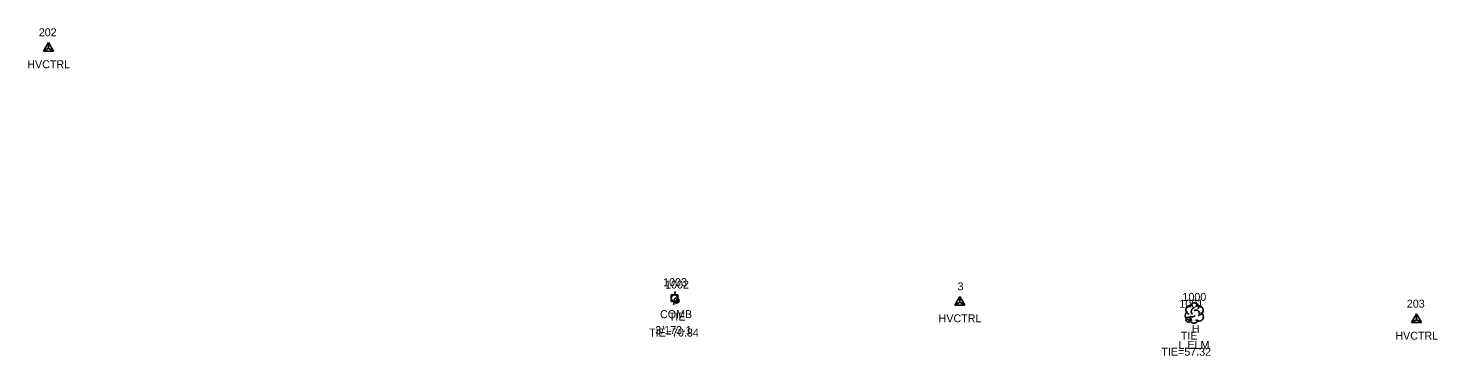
# Model space of a CAD drawing. Extents: x 1505684 to 1510253, y 730355 to 731397.
# Drawn here: x 1508083.3 to 1508435.7, y 730355.2 to 730437.1 of the extents above; entities that cross this region are included whole.
import ezdxf

# ---------------------------------------------------------------- set-up
doc = ezdxf.new("R2010")
doc.units = 0
for name, color, linetype in [('C_A', 7, 'Continuous'), ('C_C', 7, 'Continuous'), ('C_I', 7, 'Continuous'), ('CBP', 7, 'Continuous'), ('CPSM', 7, 'Continuous'), ('L_A', 7, 'Continuous'), ('L_C', 7, 'Continuous'), ('L_I', 7, 'Continuous'), ('LTD', 7, 'Continuous'), ('U_A', 7, 'Continuous'), ('U_C', 7, 'Continuous'), ('U_I', 7, 'Continuous'), ('UP', 7, 'Continuous')]:
    doc.layers.add(name, color=color, linetype=linetype)

msp = doc.modelspace()

# ---------------------------------------------------------------- linework, layer by layer
at = {"layer": 'CBP'}
for centre, radius in [((1508245.36, 730369.01), 0.625), ((1508245.36, 730369.01), 0.0833), ((1508373.34, 730364.22), 0.625), ((1508373.34, 730364.22), 0.0833)]:
    msp.add_circle(centre, radius, dxfattribs=at)
at = {"layer": 'CPSM'}
for p, q in [((1508087.13, 730431.37), (1508088.38, 730433.53)), ((1508089.63, 730431.37), (1508088.38, 730433.53)), ((1508088.38, 730432.09), (1508088.38, 730433.53)), ((1508087.13, 730431.37), (1508088.38, 730432.09)), ((1508087.13, 730431.37), (1508089.63, 730431.37)), ((1508088.38, 730432.09), (1508088.38, 730432.09)), ((1508088.38, 730432.09), (1508089.63, 730431.37)), ((1508314.94, 730367.85), (1508316.19, 730370.02)), ((1508317.44, 730367.85), (1508316.19, 730370.02)), ((1508316.19, 730368.57), (1508316.19, 730370.02)), ((1508314.94, 730367.85), (1508316.19, 730368.57)), ((1508314.94, 730367.85), (1508317.44, 730367.85)), ((1508316.19, 730368.57), (1508316.19, 730368.57)), ((1508316.19, 730368.57), (1508317.44, 730367.85)), ((1508429.12, 730363.51), (1508430.37, 730365.68)), ((1508429.12, 730363.51), (1508430.37, 730364.23)), ((1508429.12, 730363.51), (1508431.62, 730363.51)), ((1508431.62, 730363.51), (1508430.37, 730365.68)), ((1508430.37, 730364.23), (1508430.37, 730365.68)), ((1508430.37, 730364.23), (1508430.37, 730364.23)), ((1508430.37, 730364.23), (1508431.62, 730363.51))]:
    msp.add_line(p, q, dxfattribs=at)
at = {"layer": 'LTD'}
msp.add_line((1508374.78, 730365.94), (1508374.78, 730365.94), dxfattribs=at)
msp.add_line((1508374.78, 730365.94), (1508374.78, 730365.94), dxfattribs=at)
msp.add_arc((1508374.82, 730367.37), 1.05, 335.5272, 180.9563, dxfattribs=at)
for centre, major_axis, ratio, start_param, end_param in [((1508373.69, 730365.23), (0.58, -1.04), 0.959034, 3.141593, 6.283185), ((1508373.99, 730366.6), (1.21, -0.51), 0.895232, 1.570796, 4.712389), ((1508374.57, 730366.4), (-0.208, -0.792), 0.645439, 3.141593, 6.283185), ((1508375.28, 730365.77), (-0.5, 0.667), 0.989748, 3.141593, 6.283185), ((1508375.82, 730366.52), (-1.14, -0.48), 0.949671, 1.570796, 4.712389), ((1508374.78, 730364.44), (0.26, 1.06), 0.942809, 1.570796, 4.712389), ((1508374.32, 730365.19), (-0.625, -0.083), 0.423636, 0, 3.141593), ((1508375.78, 730365.1), (-1.09, 0.79), 0.841452, 1.570796, 4.712389)]:
    msp.add_ellipse(centre, major_axis=major_axis, ratio=ratio, start_param=start_param, end_param=end_param, dxfattribs=at)
at = {"layer": 'UP'}
for p, q in [((1508244.03, 730368.78), (1508244.03, 730370.44)), ((1508244.03, 730370.44), (1508245.69, 730370.44)), ((1508245.11, 730371.28), (1508244.86, 730370.44)), ((1508245.69, 730370.44), (1508245.69, 730368.78)), ((1508245.69, 730368.78), (1508244.03, 730368.78)), ((1508244.61, 730367.94), (1508244.86, 730368.78)), ((1508244.86, 730369.61), (1508244.86, 730369.61))]:
    msp.add_line(p, q, dxfattribs=at)
msp.add_circle((1508244.86, 730369.61), 0.833, dxfattribs=at)

# ---------------------------------------------------------------- texts
at = {"layer": 'C_A'}
for s, p in [('HVCTRL', (1508083.07, 730427.09)), ('TIE', (1508243.43, 730364.01)), ('HVCTRL', (1508310.88, 730363.57)), ('TIE', (1508371.42, 730359.22)), ('HVCTRL', (1508425.06, 730359.23))]:
    msp.add_text(s, height=2, dxfattribs=at).set_placement(p)
at = {"layer": 'C_C'}
for s, p in [('TIE=70.84', (1508238.51, 730360.01)), ('TIE=57.32', (1508366.57, 730355.22))]:
    msp.add_text(s, height=2, dxfattribs=at).set_placement(p)
at = {"layer": 'C_I'}
for s, p in [('202', (1508085.94, 730435.09)), ('1002', (1508242.51, 730372.01)), ('3', (1508315.62, 730371.57)), ('1001', (1508371.06, 730367.22)), ('203', (1508427.93, 730367.23))]:
    msp.add_text(s, height=2, dxfattribs=at).set_placement(p)
at = {"layer": 'L_A'}
msp.add_text('H', height=2, dxfattribs=at).set_placement((1508374.21, 730360.94))
at = {"layer": 'L_C'}
msp.add_text('L.ELM', height=2, dxfattribs=at).set_placement((1508370.86, 730356.94))
at = {"layer": 'L_I'}
msp.add_text('1000', height=2, dxfattribs=at).set_placement((1508371.84, 730368.94))
at = {"layer": 'U_A'}
msp.add_text('COMB', height=2, dxfattribs=at).set_placement((1508241.24, 730364.61))
at = {"layer": 'U_C'}
msp.add_text('3/173-1', height=2, dxfattribs=at).set_placement((1508240.04, 730360.61))
at = {"layer": 'U_I'}
msp.add_text('1003', height=2, dxfattribs=at).set_placement((1508242.01, 730372.61))

doc.saveas('drawing.dxf')
